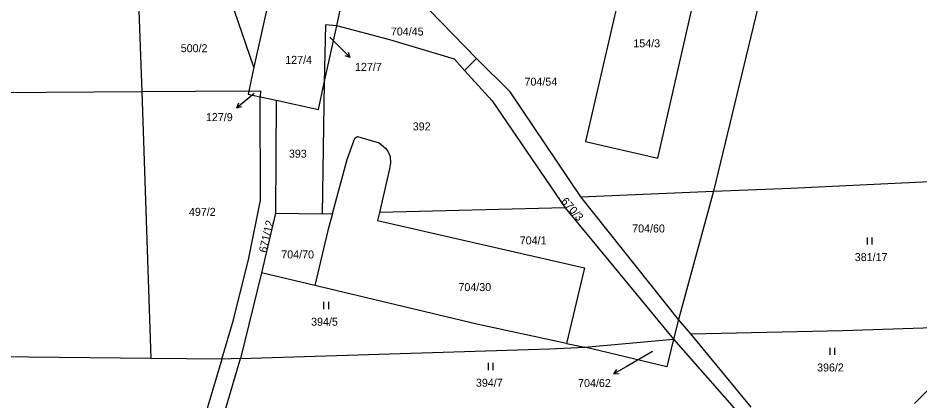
# Model space of a CAD drawing. Extents: x -747333 to -743907, y -1134120 to -1130051.
# Drawn here: x -746331.7 to -746140.1, y -1132539.7 to -1132458.3 of the extents above; entities that cross this region are included whole.
import ezdxf

# ---------------------------------------------------------------- set-up
doc = ezdxf.new("R2010")
doc.units = 0
for name, color, linetype in [('Hranice parcel', 7, 'Continuous'), ('Parcelní čísla', 7, 'Continuous'), ('Pop  PČ popisy', 7, 'Continuous'), ('Značky kultur', 7, 'Continuous')]:
    doc.layers.add(name, color=color, linetype=linetype)

msp = doc.modelspace()

# ---------------------------------------------------------------- linework, layer by layer
at = {"layer": 'Hranice parcel'}
for p, q in [((-746200.67, -1132438.78), (-746211.18, -1132484.59)), ((-746281.65, -1132468.73), (-746286.51, -1132454.45)), ((-746278.37, -1132454.12), (-746281.65, -1132468.73)), ((-746195.82, -1132488.1), (-746187.96, -1132453.69)), ((-746173.89, -1132453.04), (-746183.99, -1132495.14)), ((-746305.4, -1132474), (-746306.06, -1132454.82)), ((-746264.05, -1132460), (-746263.02, -1132455.29)), ((-746234.32, -1132466.9), (-746244.39, -1132456.6)), ((-746266.69, -1132472.07), (-746264.05, -1132460)), ((-746234.32, -1132466.9), (-746236.89, -1132469.45)), ((-746281.65, -1132468.73), (-746282.73, -1132473.84)), ((-746266.69, -1132472.07), (-746267.12, -1132499.96)), ((-746305.4, -1132474), (-746394.67, -1132474.61)), ((-746282.73, -1132473.84), (-746305.4, -1132474)), ((-746303.46, -1132530.68), (-746305.4, -1132474)), ((-746280.33, -1132475.05), (-746276.92, -1132475.8)), ((-746276.92, -1132475.8), (-746277.07, -1132499.78)), ((-746211.18, -1132484.59), (-746195.82, -1132488.1)), ((-746252.83, -1132490.35), (-746254.97, -1132499.66)), ((-746212.16, -1132496.33), (-746183.99, -1132495.14)), ((-746191.45, -1132522.4), (-746212.16, -1132496.33)), ((-746183.99, -1132495.14), (-746191.45, -1132522.4)), ((-746277.07, -1132499.78), (-746280, -1132512.49)), ((-746277.07, -1132499.78), (-746267.12, -1132499.96)), ((-746267.12, -1132499.96), (-746264.96, -1132499.91)), ((-746264.96, -1132499.91), (-746265.92, -1132503.46)), ((-746254.97, -1132499.66), (-746255.36, -1132501.33)), ((-746215.49, -1132498.68), (-746254.97, -1132499.66)), ((-746215.49, -1132498.68), (-746192.5, -1132526.63)), ((-746255.36, -1132501.33), (-746211.44, -1132511.42)), ((-746265.92, -1132503.46), (-746268.69, -1132515.2)), ((-746211.44, -1132511.42), (-746215.21, -1132527.49)), ((-746280, -1132512.49), (-746284.47, -1132530.7)), ((-746268.69, -1132515.2), (-746280, -1132512.49)), ((-746191.45, -1132522.4), (-746192.5, -1132526.63)), ((-746188.82, -1132525.47), (-746191.45, -1132522.4)), ((-746211.35, -1132528.31), (-746192.5, -1132526.63)), ((-746192.5, -1132526.63), (-746179.61, -1132541.25)), ((-746176.03, -1132541.03), (-746188.82, -1132525.47)), ((-746215.21, -1132527.49), (-746211.35, -1132528.31)), ((-746303.46, -1132530.68), (-746395.66, -1132529.71)), ((-746288.46, -1132530.84), (-746303.46, -1132530.68)), ((-746288.46, -1132530.84), (-746292.8, -1132545.37)), ((-746288.6, -1132544.53), (-746284.47, -1132530.7)), ((-746284.47, -1132530.7), (-746288.46, -1132530.84))]:
    msp.add_line(p, q, dxfattribs=at)
for points in [[(-746264.05, -1132460), (-746266.4, -1132459.73), (-746266.69, -1132472.07)], [(-746236.89, -1132469.45), (-746239, -1132467.07), (-746252.73, -1132462.97), (-746264.05, -1132460)], [(-746212.16, -1132496.33), (-746227.19, -1132474.03), (-746234.32, -1132466.9)], [(-746236.89, -1132469.45), (-746231.04, -1132475.95), (-746215.49, -1132498.68)], [(-746276.92, -1132475.8), (-746267.94, -1132477.77), (-746266.69, -1132472.07)], [(-746288.46, -1132530.84), (-746285.96, -1132522.49), (-746282.68, -1132509.35), (-746280.25, -1132497.07), (-746280.33, -1132475.05)], [(-746282.73, -1132473.84), (-746282.87, -1132474.49), (-746280.33, -1132475.05)], [(-746282.73, -1132473.84), (-746280.27, -1132473.8), (-746280.33, -1132475.05)], [(-746264.96, -1132499.91), (-746261.83, -1132488.38), (-746260.18, -1132483.84), (-746259.65, -1132483.52), (-746255.06, -1132484.84), (-746253.66, -1132485.96), (-746253.21, -1132486.65), (-746252.71, -1132487.79), (-746252.61, -1132489.07), (-746252.83, -1132490.35)], [(-746183.99, -1132495.14), (-746167.55, -1132494.48), (-746101.3, -1132491.27)], [(-746215.21, -1132527.49), (-746234.3, -1132523.43), (-746268.69, -1132515.2)], [(-746188.82, -1132525.47), (-746156.56, -1132524.76), (-746133, -1132523.94), (-746125.41, -1132524.23)], [(-746125.41, -1132524.23), (-746127.95, -1132526.82), (-746141.33, -1132540.28)], [(-746192.5, -1132526.63), (-746193.95, -1132532.5), (-746211.35, -1132528.31)], [(-746284.47, -1132530.7), (-746218.78, -1132528.63), (-746211.35, -1132528.31)]]:
    msp.add_lwpolyline(points, dxfattribs=at)
at = {"layer": 'Pop  PČ popisy'}
for p, q in [((-746265.51, -1132462.37), (-746263.28, -1132464.6)), ((-746263.28, -1132464.6), (-746261.158, -1132466.722)), ((-746261.158, -1132466.722), (-746261.512, -1132465.66)), ((-746261.158, -1132466.722), (-746262.22, -1132466.368)), ((-746282.95, -1132475.51), (-746285.282, -1132477.399)), ((-746281.58, -1132474.39), (-746282.95, -1132475.51)), ((-746285.282, -1132477.399), (-746284.819, -1132476.379)), ((-746285.282, -1132477.399), (-746284.189, -1132477.157)), ((-746196.96, -1132529.25), (-746202.56, -1132532.45)), ((-746202.56, -1132532.45), (-746205.159, -1132533.95)), ((-746205.159, -1132533.95), (-746204.542, -1132533.016)), ((-746205.159, -1132533.95), (-746204.041, -1132533.883))]:
    msp.add_line(p, q, dxfattribs=at)
at = {"layer": 'Značky kultur'}
for p, q in [((-746151.311, -1132506.45), (-746151.311, -1132504.95)), ((-746150.31, -1132506.45), (-746150.31, -1132504.95)), ((-746266.751, -1132520.19), (-746266.751, -1132518.69)), ((-746265.75, -1132520.19), (-746265.75, -1132518.69)), ((-746159.241, -1132529.92), (-746159.241, -1132528.42)), ((-746158.24, -1132529.92), (-746158.24, -1132528.42)), ((-746231.811, -1132533.16), (-746231.811, -1132531.66)), ((-746230.81, -1132533.16), (-746230.81, -1132531.66))]:
    msp.add_line(p, q, dxfattribs=at)

# ---------------------------------------------------------------- texts
at = {"layer": 'Parcelní čísla'}
for s, p in [('704/45', (-746252.54, -1132462.03)), ('500/2', (-746297.183, -1132465.58)), ('154/3', (-746201.03, -1132464.54)), ('127/4', (-746274.98, -1132468.06)), ('127/7', (-746260.16, -1132469.553)), ('704/54', (-746224.15, -1132472.69)), ('127/9', (-746291.826, -1132480.233)), ('392', (-746247.89, -1132482.21)), ('393', (-746274.2, -1132488.01)), ('497/2', (-746295.443, -1132500.38)), ('704/60', (-746201.28, -1132503.91)), ('704/1', (-746225.163, -1132506.45)), ('704/70', (-746275.825, -1132509.43)), ('381/17', (-746153.99, -1132510)), ('704/30', (-746238.185, -1132516.38)), ('394/5', (-746269.49, -1132523.74)), ('396/2', (-746162, -1132533.47)), ('394/7', (-746234.47, -1132536.71)), ('704/62', (-746212.771, -1132536.773))]:
    msp.add_text(s, height=1.7, dxfattribs=at).set_placement(p)
for s, rotation, p in [('670/3', 311, (-746216.481, -1132497.357)), ('671/12', 77, (-746278.955, -1132508.312))]:
    msp.add_text(s, height=1.7, rotation=rotation, dxfattribs=at).set_placement(p)

doc.saveas('drawing.dxf')
